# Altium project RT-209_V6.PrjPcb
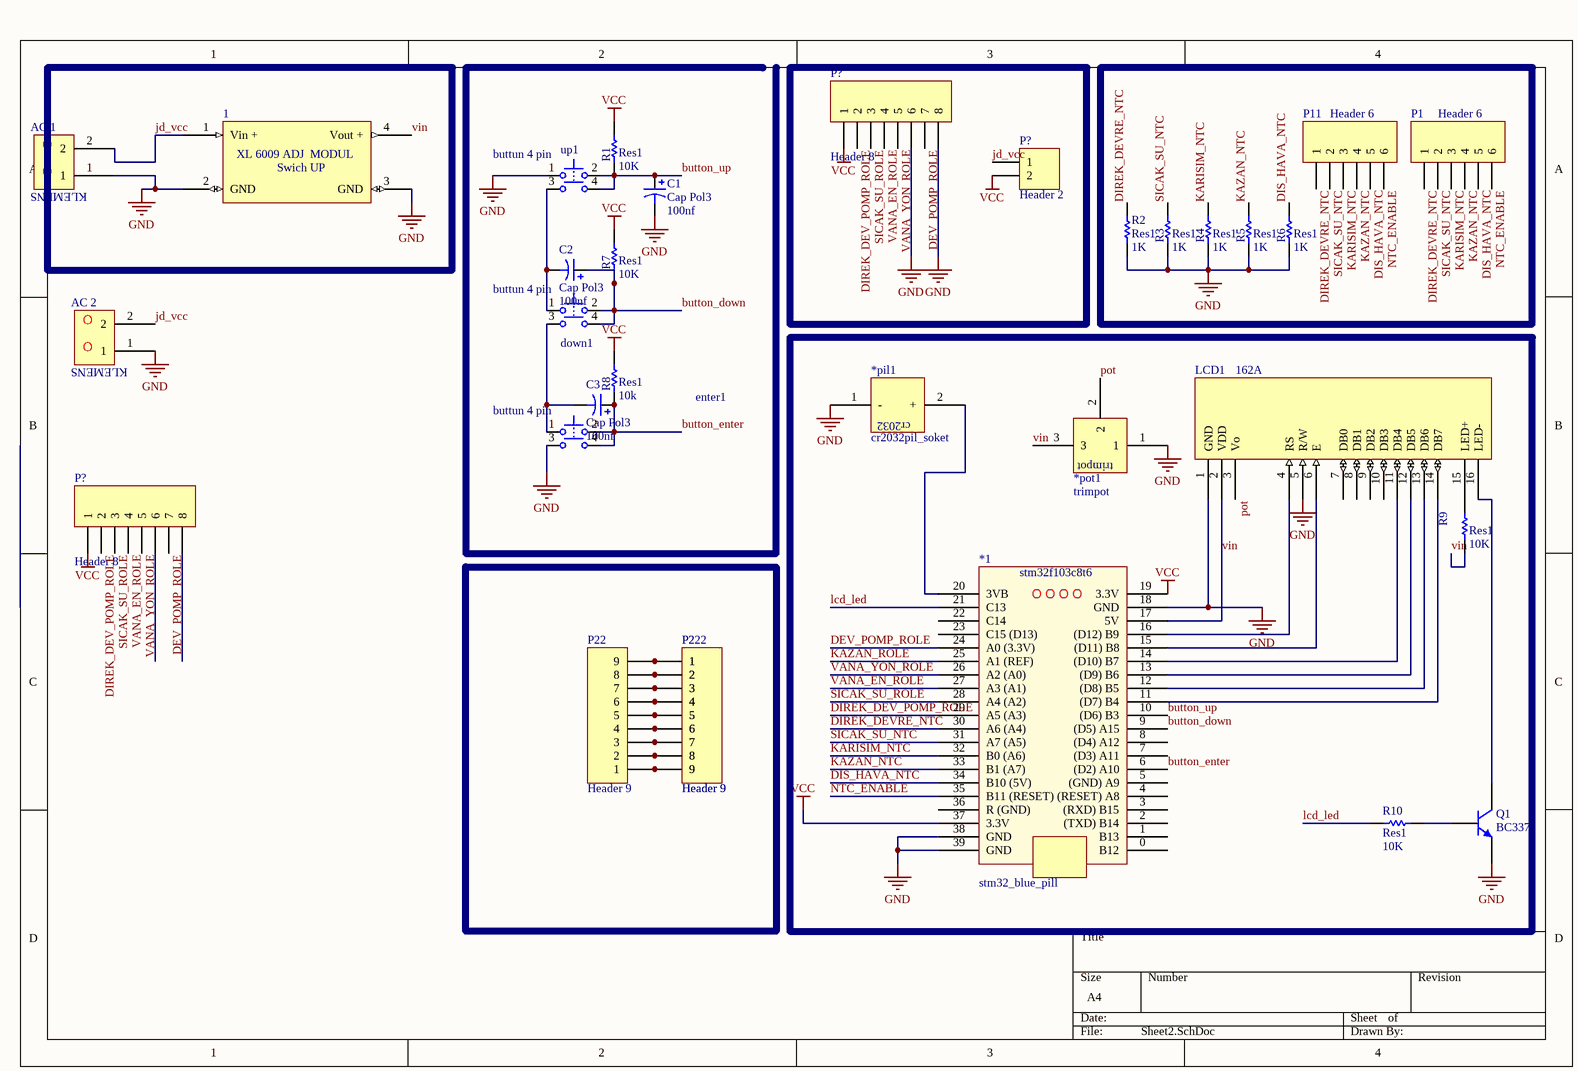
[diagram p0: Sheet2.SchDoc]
1 sheet, 32 parts. Net scope: global (net labels, ports and power ports of the same name join across sheets).
Board file: PCB1.PcbDoc

## Sheet Sheet2.SchDoc
size A4

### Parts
(Parts that share a designator on the sheet are numbered #1, #2 ... from top to bottom, then left to right.)
1  (no value)  [mt3608]
*1  stm32_blue_pill  [STM32_BLUE_PIL]
*pil1  cr2032pil_soket  [cr2032 holder]
*pot1  trimpot  [trimpot]
AC_1  (no value)  [klemens 200 mil]
AC_2  (no value)  [klemens 200 mil]
C1  Cap Pol3  value 100nf  [Resistor smd]
C2  Cap Pol3  value 100nf  [Resistor smd]
C3  Cap Pol3  value 100nf  [Resistor smd]
down1  buttun 4 pin  [button]
enter1  buttun 4 pin  [button]
LCD1  162A  [lcd_benim_kullndigim]
P1  Header 6  [klemens 6X]
P2  Header 9  [klemens 9X]
P11  Header 6  [klemens 6X]
P22  Header 9  [klemens 9X]
P222  Header 9  [klemens 9X]
P?#1  Header 8  [HDR1X8]
P?#2  Header 2  [HDR1X2]
P?#3  Header 8  [HDR1X8]
Q1  BC337  [bc337]
R1  Res1  value 10K  [Resistor smd]
R2  Res1  value 1K  [Resistor smd]
R3  Res1  value 1K  [Resistor smd]
R4  Res1  value 1K  [Resistor smd]
R5  Res1  value 1K  [Resistor smd]
R6  Res1  value 1K  [Resistor smd]
R7  Res1  value 10K  [Resistor smd]
R8  Res1  value 10k  [Resistor smd]
R9  Res1  value 10K  [Resistor smd]
R10  Res1  value 10K  [Resistor smd]
up1  buttun 4 pin  [button]

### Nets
GND: 1.2(GND) 1.3(GND) *1.18(GND) *1.38(GND) *1.39(GND) *pil1.1(-) *pot1.1 AC_1.1 AC_2.1 C1.2 enter1.3 LCD1.1(GND) LCD1.5(R/W) P?#1.6 P?#1.8 Q1.1(E) R2.2 R3.2 R4.2 R5.2 R6.2 up1.1
VCC: *1.19(3.3V) *1.37(3.3V) P?#1.1 P?#2.2 P?#3.1 R1.1 R7.1 R8.1
button_down: *1.9((D5)_A15) C2.1 down1.2 down1.4 R7.2
button_enter: *1.6((D2)_A10) C3.1 enter1.2 enter1.4 R8.2
button_up: *1.10((D6)_B3) C1.1 R1.2 up1.2 up1.4
DEV_POMP_ROLE: *1.24(A0_(3.3V)) P?#1.7 P?#3.7
DIREK_DEV_POMP_ROLE: *1.29(A5_(A3)) P?#1.2 P?#3.2
DIREK_DEVRE_NTC: *1.30(A6_(A4)) P1.1 P11.1 R2.1
DIS_HAVA_NTC: *1.34(B10_(5V)) P1.5 P11.5 R6.1
jd_vcc: 1.1(Vin_+) AC_1.2 AC_2.2 P?#2.1
KARISIM_NTC: *1.32(B0_(A6)) P1.3 P11.3 R4.1
KAZAN_NTC: *1.33(B1_(A7)) P1.4 P11.4 R5.1
KAZAN_ROLE: *1.25(A1_(REF))
lcd_led: *1.21(C13) R10.2
NTC_ENABLE: *1.35(B11_(RESET)) P1.6 P11.6
pot: *pot1.2 LCD1.3(Vo)
SICAK_SU_NTC: *1.31(A7_(A5)) P1.2 P11.2 R3.1
SICAK_SU_ROLE: *1.28(A4_(A2)) P?#1.3 P?#3.3
VANA_EN_ROLE: *1.27(A3_(A1)) P?#1.4 P?#3.4
VANA_YON_ROLE: *1.26(A2_(A0)) P?#1.5 P?#3.5
vin: 1.4(Vout_+) *1.17(5V) *pot1.3 LCD1.2(VDD) R9.2
Net*1_11: *1.11((D7)_B4) LCD1.14(DB7)
Net*1_12: *1.12((D8)_B5) LCD1.13(DB6)
Net*1_13: *1.13((D9)_B6) LCD1.12(DB5)
Net*1_14: *1.14((D10)_B7) LCD1.11(DB4)
Net*1_15: *1.15((D11)_B8) LCD1.6(E)
Net*1_16: *1.16((D12)_B9) LCD1.4(RS)
Net*1_20: *1.20(3VB) *pil1.2(+)
NetC2_2: C2.2 down1.1 up1.3
NetC3_2: C3.2 down1.3 enter1.1
NetLCD1_15: LCD1.15(LED+) R9.1
NetLCD1_16: LCD1.16(LED-) Q1.3(C)
NetP2_1: P2.1 P22.9 P222.1
NetP2_2: P2.2 P22.8 P222.2
NetP2_3: P2.3 P22.7 P222.3
NetP2_4: P2.4 P22.6 P222.4
NetP2_5: P2.5 P22.5 P222.5
NetP2_6: P2.6 P22.4 P222.6
NetP2_7: P2.7 P22.3 P222.7
NetP2_8: P2.8 P22.2 P222.8
NetP2_9: P2.9 P22.1 P222.9
NetQ1_2: Q1.2(B) R10.1

Not connected (* = marked no-connect by the designer): *1 0(B12) 1(B13) 2((TXD)_B14) 3((RXD)_B15) 4((RESET)_A8) 5((GND)_A9) 7((D3)_A11) 8((D4)_A12) 22(C14) 23(C15_(D13)) 36(R_(GND)); LCD1 7(DB0) 8(DB1) 9(DB2) 10(DB3); P?#3 6 8

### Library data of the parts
1 = swich up adj regulator modul
AC_1 AC_2 = klemens2li
C1-C3 = Cap Pol3: Polarized Capacitor (Surface Mount)
LCD1 = 162A: 16 char * 2 line LCD character display with b/light
P1 P11 = Header 6: Header, 6-Pin
P2 P22 P222 = Header 9: Header, 9-Pin
P?#1 P?#3 = Header 8: Header, 8-Pin
P?#2 = Header 2: Header, 2-Pin
Q1 = BC337: NPN General Purpose Amplifier
R1-R10 = Res1: Resistor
